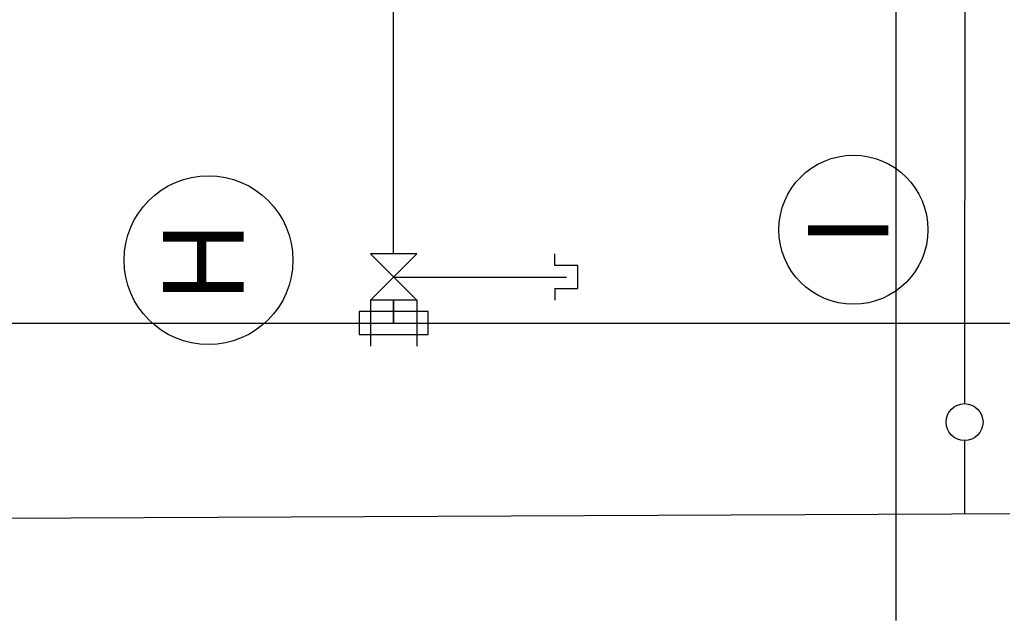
# Model space of a CAD drawing. Extents: x -264031 to -263588, y -1242281 to -1242059.
# Drawn here: x -263871.58 to -263860.91, y -1242253.37 to -1242246.85 of the extents above; entities that cross this region are included whole.
import ezdxf

# ---------------------------------------------------------------- set-up
doc = ezdxf.new("R2010")
doc.units = 0
for name, color, linetype in [('HESCON_OSI_STAVBY_KFA', 7, 'Continuous'), ('KFA_2D_SITUACIA_DSP', 7, 'Continuous'), ('KFA_JESTV_IS_DSP_-_KANAL_SPLASK', 7, 'Continuous')]:
    doc.layers.add(name, color=color, linetype=linetype)

msp = doc.modelspace()

# ---------------------------------------------------------------- linework, layer by layer
at = {"layer": 'HESCON_OSI_STAVBY_KFA'}
for centre, radius in [((-263862.528, -1242249.126), 0.809), ((-263869.528, -1242249.457), 0.916)]:
    msp.add_circle(centre, radius, dxfattribs=at)
at = {"layer": 'KFA_2D_SITUACIA_DSP'}
for p, q in [((-263867.518, -1242249.39), (-263867.518, -1242235.757)), ((-263861.318, -1242235.757), (-263861.321, -1242251.015)), ((-263862.068, -1242241.132), (-263862.068, -1242253.368)), ((-263867.268, -1242249.39), (-263867.768, -1242249.39)), ((-263867.768, -1242249.89), (-263867.268, -1242249.39)), ((-263867.768, -1242249.39), (-263867.268, -1242249.89)), ((-263865.768, -1242249.515), (-263865.768, -1242249.39)), ((-263865.518, -1242249.515), (-263865.768, -1242249.515)), ((-263865.518, -1242249.765), (-263865.518, -1242249.515)), ((-263867.518, -1242249.64), (-263865.643, -1242249.64)), ((-263865.768, -1242249.765), (-263865.768, -1242249.89)), ((-263865.768, -1242249.765), (-263865.518, -1242249.765)), ((-263867.268, -1242249.89), (-263867.768, -1242249.89)), ((-263867.768, -1242249.89), (-263867.768, -1242250.39)), ((-263867.518, -1242250.14), (-263867.518, -1242249.89)), ((-263867.518, -1242249.89), (-263867.518, -1242250.14)), ((-263867.268, -1242249.89), (-263867.268, -1242250.39)), ((-263867.143, -1242250.015), (-263867.893, -1242250.015)), ((-263867.893, -1242250.015), (-263867.893, -1242250.265)), ((-263867.143, -1242250.265), (-263867.143, -1242250.015)), ((-263924.143, -1242250.14), (-263788.143, -1242250.14)), ((-263867.893, -1242250.265), (-263867.143, -1242250.265)), ((-263861.321, -1242251.415), (-263861.321, -1242252.215))]:
    msp.add_line(p, q, dxfattribs=at)
msp.add_circle((-263861.321, -1242251.215), 0.2, dxfattribs=at)
at = {"layer": 'KFA_JESTV_IS_DSP_-_KANAL_SPLASK'}
msp.add_line((-263832.703, -1242252.091), (-263876.504, -1242252.281), dxfattribs=at)

# ---------------------------------------------------------------- texts
at = {"layer": 'HESCON_OSI_STAVBY_KFA'}
for s, p in [('H', (-263869.147, -1242249.898)), ('I', (-263862.147, -1242249.296))]:
    msp.add_text(s, height=0.875, rotation=90, dxfattribs=at).set_placement(p)

doc.saveas('drawing.dxf')
